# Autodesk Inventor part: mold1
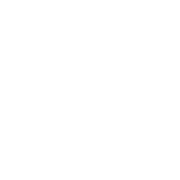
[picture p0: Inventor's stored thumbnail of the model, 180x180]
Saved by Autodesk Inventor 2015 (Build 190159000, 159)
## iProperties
Created: 2016-02
Part Number: mold1
Material: Polycarbonate, Smoke
Document SubType Name: Modeling
Designer: Hafliði
Density: 1.2 g/cm^3
Appearance: Polycarbonate - Smoked
Mass: 15993.6 g
Surface Area: 3948 cm^2
Volume: 13328 cm^3
Author: Hafliði
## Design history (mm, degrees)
sketch "Sketch1"
  geometry: L1 (-280, 70)-(280, 70); L2 (280, 70)-(280, -70); L3 (280, -70)-(-280, -70); L4 (-280, -70)-(-280, 70); L5 (-280, 70)-(280, -70); L6 (280, 70)-(-280, -70); 1 further point
  constraints: 12 end point, 2 midpoint, 2 parallel, 1 horizontal, 1 perpendicular
  dimensions: "d0" = 560 distance of L2.end L3.end; "d1" = 140 distance of L1.end L2.end
extrude "Extrusion1" new body sketch "Sketch1" distance "d2" = 170; taper "d3" = 0 deg
body "Solid1"
